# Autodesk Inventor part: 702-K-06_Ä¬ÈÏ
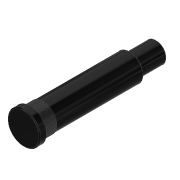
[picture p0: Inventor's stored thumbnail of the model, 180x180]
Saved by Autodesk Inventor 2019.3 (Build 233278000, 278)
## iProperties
Created: 2010-06
Part Number: 702-K-06_Ä¬ÈÏ
Material: Ogólny
Document SubType Name: Modeling
Designer: CADENGINEERING4
Density: 1 g/cm^3
Appearance: Gładki — czarny
Author: CADENGINEERING4
Revision Number: ÈÎºÎ
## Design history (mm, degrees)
feature "NONE"
node "Bryła1"
